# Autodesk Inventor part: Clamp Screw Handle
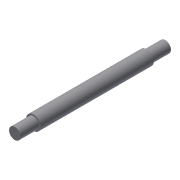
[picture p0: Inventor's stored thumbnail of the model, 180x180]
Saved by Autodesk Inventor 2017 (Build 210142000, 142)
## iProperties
Shininess: 77.0
Length Units: 11269
Angle Units: 11279
Time Units: 11290
Mass Units: 11283
Length Display Precision: 3
Angle Display Precision: 2
Compacted: True
Created: 2002-02
Part Number: Clamp Screw Handle
Document SubType Name: Modeling
Designer: ***
Density: 1 g/cm^3
Material: Generic
Mass: 7.51155 g
Surface Area: 32.9239 cm^2
Volume: 7.51155 cm^3
Appearance: Default
Density: 0.0
Volumn: 0.0
Area: 0.0
PropertySet Name: Model Information
Control State: 0
Master: False
Checked Out: False
Author: ***
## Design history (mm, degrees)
sketch "Sketch1"
  geometry: L1 (0, 105)-(4, 105); L2 (4, 105)-(4, 92); L3 (4, 92)-(5, 92); L4 (5, 92)-(5, 13); L5 (5, 13)-(4, 13); L6 (4, 13)-(4, 0); L7 (4, 0)-(0, 0); L8 (0, 0)-(0, 105)
  constraints: 16 end point, 5 parallel, 2 equal length, 1 collinear, 1 horizontal, 1 perpendicular
  dimensions: "d0" = 10 diameter of L4 L8; "d1" = 8 diameter of L2 L8; "d2" = 13 distance of L1.end L2.end; "d3" = 79 distance of L3.end L4.end
revolve "Revolution1" sketch "Sketch1" stored, may be unused: angle "d4" = 90 deg
body "Solid1"
